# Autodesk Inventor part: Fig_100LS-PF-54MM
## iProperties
Created: 2011-12
Part Number: Fig_100LS-PF-54MM
Document SubType Name: Modeling
Designer: D Cole
Density: 1 g/cm^3
Translation Standard: STEP AP214IS
File Name: P:\Fastrack\53972_CRANE 3D\Press Fit\HATTERSLEY\100LS-PF\54MM\54mm.stp
Preprocessor: Autodesk Inventor 2008
Postprocessor: Build: 342, Release: 2008 SP3 - Date: Tue 05/27/2008
Sent Units: MILLIMETERS
Uncertainty: 0.01
Author: D Cole
